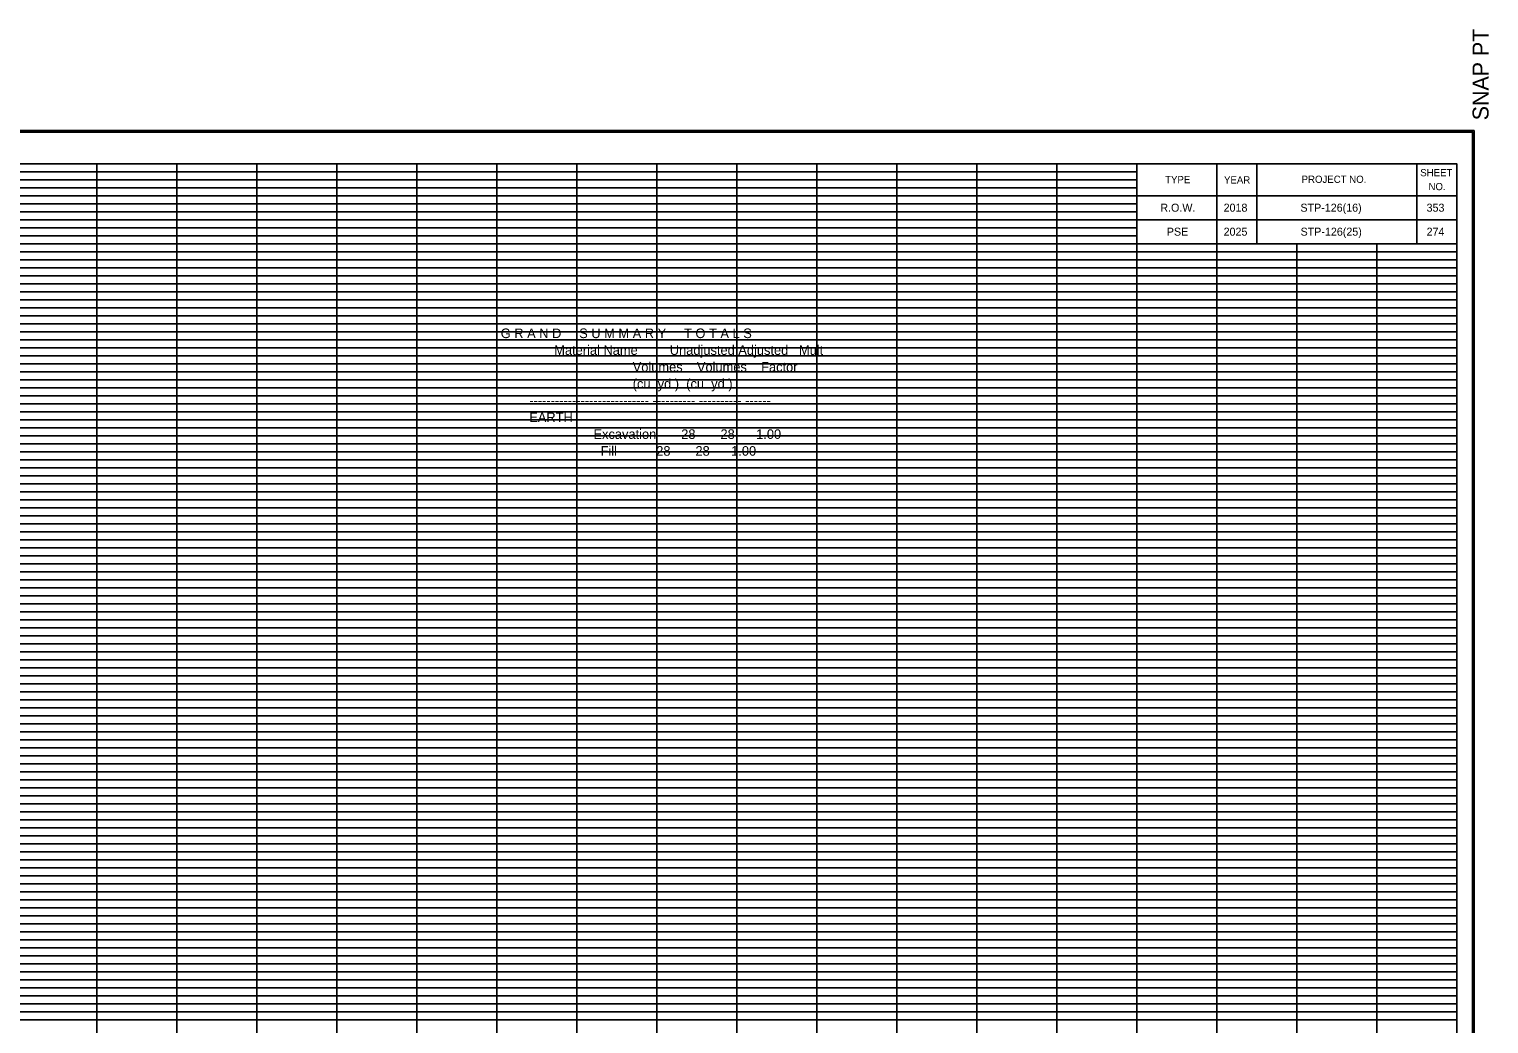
# Model space of a CAD drawing. Extents: x 980 to 1324, y 978 to 1227.
# Drawn here: x 1141.5 to 1324, y 1102.5 to 1226.8 of the extents above; entities that cross this region are included whole.
import ezdxf

# ---------------------------------------------------------------- set-up
doc = ezdxf.new("R2010")
doc.units = 0
for name, color, linetype in [('DESIGN - SCRATCH - User 1', 7, 'Continuous'), ('DESIGN - SHEET - Corner Text', 7, 'Continuous'), ('DESIGN - SHEET - Light Grid', 7, 'Continuous'), ('DESIGN - SHEET - Linework', 7, 'Continuous'), ('DESIGN - SHEET - Plot Shape', 7, 'Continuous'), ('DESIGN - TYPICAL - Finished Grade and Subgrade', 7, 'Continuous'), ('DESIGN - TYPICAL - Text', 7, 'Continuous')]:
    doc.layers.add(name, color=color, linetype=linetype)

# ---------------------------------------------------------------- blocks, each defined once
blk = doc.blocks.new('XSTSHT')
at = {"layer": 'DESIGN - SCRATCH - User 1'}
for p, q in [((28.5, 20.45), (28.5, 20.45)), ((29.24, 20.45), (29.24, 20.45)), ((30.49, 20.45), (30.49, 20.45)), ((31.74, 20.45), (31.74, 20.45)), ((28.5, 20.15), (28.5, 20.15)), ((29.24, 20.15), (29.24, 20.15)), ((30.49, 20.15), (30.49, 20.15)), ((31.74, 20.15), (31.74, 20.15))]:
    blk.add_line(p, q, dxfattribs=at)
at = {"layer": 'DESIGN - SHEET - Light Grid'}
for p, q in [((8, 20.9), (16, 20.9)), ((8, 20.8), (16, 20.8)), ((16, 20.9), (24, 20.9)), ((16, 20.8), (24, 20.8)), ((24, 20.9), (28, 20.9)), ((24, 20.8), (28, 20.8)), ((8, 20.7), (16, 20.7)), ((16, 20.7), (24, 20.7)), ((24, 20.7), (28, 20.7)), ((8, 20.6), (16, 20.6)), ((8, 20.5), (16, 20.5)), ((16, 20.6), (24, 20.6)), ((16, 20.5), (24, 20.5)), ((24, 20.6), (28, 20.6)), ((24, 20.5), (28, 20.5)), ((8, 20.4), (16, 20.4)), ((8, 20.3), (16, 20.3)), ((16, 20.4), (24, 20.4)), ((16, 20.3), (24, 20.3)), ((24, 20.4), (28, 20.4)), ((24, 20.3), (28, 20.3)), ((8, 20.2), (16, 20.2)), ((8, 20.1), (16, 20.1)), ((16, 20.2), (24, 20.2)), ((16, 20.1), (24, 20.1)), ((24, 20.2), (28, 20.2)), ((24, 20.1), (28, 20.1)), ((8, 19.9), (16, 19.9)), ((16, 19.9), (24, 19.9)), ((24, 19.9), (32, 19.9)), ((8, 19.8), (16, 19.8)), ((16, 19.8), (24, 19.8)), ((24, 19.8), (32, 19.8)), ((8, 19.7), (16, 19.7)), ((8, 19.6), (16, 19.6)), ((16, 19.7), (24, 19.7)), ((16, 19.6), (24, 19.6)), ((24, 19.7), (32, 19.7)), ((24, 19.6), (32, 19.6)), ((8, 19.5), (16, 19.5)), ((8, 19.4), (16, 19.4)), ((16, 19.5), (24, 19.5)), ((16, 19.4), (24, 19.4)), ((24, 19.5), (32, 19.5)), ((24, 19.4), (32, 19.4)), ((8, 19.3), (16, 19.3)), ((8, 19.2), (16, 19.2)), ((16, 19.3), (24, 19.3)), ((16, 19.2), (24, 19.2)), ((24, 19.3), (32, 19.3)), ((24, 19.2), (32, 19.2)), ((8, 19.1), (16, 19.1)), ((16, 19.1), (24, 19.1)), ((24, 19.1), (32, 19.1)), ((8, 18.9), (16, 18.9)), ((8, 18.8), (16, 18.8)), ((16, 18.9), (24, 18.9)), ((16, 18.8), (24, 18.8)), ((24, 18.9), (32, 18.9)), ((24, 18.8), (32, 18.8)), ((8, 18.7), (16, 18.7)), ((16, 18.7), (24, 18.7)), ((24, 18.7), (32, 18.7)), ((8, 18.6), (16, 18.6)), ((8, 18.5), (16, 18.5)), ((16, 18.6), (24, 18.6)), ((16, 18.5), (24, 18.5)), ((24, 18.6), (32, 18.6)), ((24, 18.5), (32, 18.5)), ((8, 18.4), (16, 18.4)), ((8, 18.3), (16, 18.3)), ((16, 18.4), (24, 18.4)), ((16, 18.3), (24, 18.3)), ((24, 18.4), (32, 18.4)), ((24, 18.3), (32, 18.3)), ((8, 18.2), (16, 18.2)), ((8, 18.1), (16, 18.1)), ((16, 18.2), (24, 18.2)), ((16, 18.1), (24, 18.1)), ((24, 18.2), (32, 18.2)), ((24, 18.1), (32, 18.1)), ((8, 17.9), (16, 17.9)), ((16, 17.9), (24, 17.9)), ((24, 17.9), (32, 17.9)), ((8, 17.8), (16, 17.8)), ((8, 17.7), (16, 17.7)), ((16, 17.8), (24, 17.8)), ((16, 17.7), (24, 17.7)), ((24, 17.8), (32, 17.8)), ((24, 17.7), (32, 17.7)), ((8, 17.6), (16, 17.6)), ((16, 17.6), (24, 17.6)), ((24, 17.6), (32, 17.6)), ((8, 17.5), (16, 17.5)), ((8, 17.4), (16, 17.4)), ((16, 17.5), (24, 17.5)), ((16, 17.4), (24, 17.4)), ((24, 17.5), (32, 17.5)), ((24, 17.4), (32, 17.4)), ((8, 17.3), (16, 17.3)), ((8, 17.2), (16, 17.2)), ((16, 17.3), (24, 17.3)), ((16, 17.2), (24, 17.2)), ((24, 17.3), (32, 17.3)), ((24, 17.2), (32, 17.2)), ((8, 17.1), (16, 17.1)), ((16, 17.1), (24, 17.1)), ((24, 17.1), (32, 17.1)), ((8, 16.9), (16, 16.9)), ((8, 16.8), (16, 16.8)), ((16, 16.9), (24, 16.9)), ((16, 16.8), (24, 16.8)), ((24, 16.9), (32, 16.9)), ((24, 16.8), (32, 16.8)), ((8, 16.7), (16, 16.7)), ((16, 16.7), (24, 16.7)), ((24, 16.7), (32, 16.7)), ((8, 16.6), (16, 16.6)), ((8, 16.5), (16, 16.5)), ((16, 16.6), (24, 16.6)), ((16, 16.5), (24, 16.5)), ((24, 16.6), (32, 16.6)), ((24, 16.5), (32, 16.5)), ((8, 16.4), (16, 16.4)), ((8, 16.3), (16, 16.3)), ((16, 16.4), (24, 16.4)), ((16, 16.3), (24, 16.3)), ((24, 16.4), (32, 16.4)), ((24, 16.3), (32, 16.3)), ((8, 16.2), (16, 16.2)), ((8, 16.1), (16, 16.1)), ((16, 16.2), (24, 16.2)), ((16, 16.1), (24, 16.1)), ((24, 16.2), (32, 16.2)), ((24, 16.1), (32, 16.1)), ((8, 15.9), (16, 15.9)), ((16, 15.9), (24, 15.9)), ((24, 15.9), (32, 15.9)), ((8, 15.8), (16, 15.8)), ((8, 15.7), (16, 15.7)), ((16, 15.8), (24, 15.8)), ((16, 15.7), (24, 15.7)), ((24, 15.8), (32, 15.8)), ((24, 15.7), (32, 15.7)), ((8, 15.6), (16, 15.6)), ((16, 15.6), (24, 15.6)), ((24, 15.6), (32, 15.6)), ((8, 15.5), (16, 15.5)), ((8, 15.4), (16, 15.4)), ((16, 15.5), (24, 15.5)), ((16, 15.4), (24, 15.4)), ((24, 15.5), (32, 15.5)), ((24, 15.4), (32, 15.4)), ((8, 15.3), (16, 15.3)), ((8, 15.2), (16, 15.2)), ((16, 15.3), (24, 15.3)), ((16, 15.2), (24, 15.2)), ((24, 15.3), (32, 15.3)), ((24, 15.2), (32, 15.2)), ((8, 15.1), (16, 15.1)), ((16, 15.1), (24, 15.1)), ((24, 15.1), (32, 15.1)), ((8, 14.9), (16, 14.9)), ((8, 14.8), (16, 14.8)), ((16, 14.9), (24, 14.9)), ((16, 14.8), (24, 14.8)), ((24, 14.9), (32, 14.9)), ((24, 14.8), (32, 14.8)), ((8, 14.7), (16, 14.7)), ((8, 14.6), (16, 14.6)), ((16, 14.7), (24, 14.7)), ((16, 14.6), (24, 14.6)), ((24, 14.7), (32, 14.7)), ((24, 14.6), (32, 14.6)), ((8, 14.5), (16, 14.5)), ((16, 14.5), (24, 14.5)), ((24, 14.5), (32, 14.5)), ((8, 14.4), (16, 14.4)), ((8, 14.3), (16, 14.3)), ((16, 14.4), (24, 14.4)), ((16, 14.3), (24, 14.3)), ((24, 14.4), (32, 14.4)), ((24, 14.3), (32, 14.3)), ((8, 14.2), (16, 14.2)), ((8, 14.1), (16, 14.1)), ((16, 14.2), (24, 14.2)), ((16, 14.1), (24, 14.1)), ((24, 14.2), (32, 14.2)), ((24, 14.1), (32, 14.1)), ((8, 13.9), (16, 13.9)), ((16, 13.9), (24, 13.9)), ((24, 13.9), (32, 13.9)), ((8, 13.8), (16, 13.8)), ((8, 13.7), (16, 13.7)), ((16, 13.8), (24, 13.8)), ((16, 13.7), (24, 13.7)), ((24, 13.8), (32, 13.8)), ((24, 13.7), (32, 13.7)), ((8, 13.6), (16, 13.6)), ((16, 13.6), (24, 13.6)), ((24, 13.6), (32, 13.6)), ((8, 13.5), (16, 13.5)), ((8, 13.4), (16, 13.4)), ((16, 13.5), (24, 13.5)), ((16, 13.4), (24, 13.4)), ((24, 13.5), (32, 13.5)), ((24, 13.4), (32, 13.4)), ((8, 13.3), (16, 13.3)), ((8, 13.2), (16, 13.2)), ((16, 13.3), (24, 13.3)), ((16, 13.2), (24, 13.2)), ((24, 13.3), (32, 13.3)), ((24, 13.2), (32, 13.2)), ((8, 13.1), (16, 13.1)), ((16, 13.1), (24, 13.1)), ((24, 13.1), (32, 13.1)), ((8, 12.9), (16, 12.9)), ((8, 12.8), (16, 12.8)), ((16, 12.9), (24, 12.9)), ((16, 12.8), (24, 12.8)), ((24, 12.9), (32, 12.9)), ((24, 12.8), (32, 12.8)), ((8, 12.7), (16, 12.7)), ((8, 12.6), (16, 12.6)), ((16, 12.7), (24, 12.7)), ((16, 12.6), (24, 12.6)), ((24, 12.7), (32, 12.7)), ((24, 12.6), (32, 12.6)), ((8, 12.5), (16, 12.5)), ((16, 12.5), (24, 12.5)), ((24, 12.5), (32, 12.5)), ((8, 12.4), (16, 12.4)), ((8, 12.3), (16, 12.3)), ((16, 12.4), (24, 12.4)), ((16, 12.3), (24, 12.3)), ((24, 12.4), (32, 12.4)), ((24, 12.3), (32, 12.3)), ((8, 12.2), (16, 12.2)), ((8, 12.1), (16, 12.1)), ((16, 12.2), (24, 12.2)), ((16, 12.1), (24, 12.1)), ((24, 12.2), (32, 12.2)), ((24, 12.1), (32, 12.1)), ((8, 11.9), (16, 11.9)), ((16, 11.9), (24, 11.9)), ((24, 11.9), (32, 11.9)), ((8, 11.8), (16, 11.8)), ((8, 11.7), (16, 11.7)), ((16, 11.8), (24, 11.8)), ((16, 11.7), (24, 11.7)), ((24, 11.8), (32, 11.8)), ((24, 11.7), (32, 11.7)), ((8, 11.6), (16, 11.6)), ((8, 11.5), (16, 11.5)), ((16, 11.6), (24, 11.6)), ((16, 11.5), (24, 11.5)), ((24, 11.6), (32, 11.6)), ((24, 11.5), (32, 11.5)), ((8, 11.4), (16, 11.4)), ((16, 11.4), (24, 11.4)), ((24, 11.4), (32, 11.4)), ((8, 11.3), (16, 11.3)), ((8, 11.2), (16, 11.2)), ((16, 11.3), (24, 11.3)), ((16, 11.2), (24, 11.2)), ((24, 11.3), (32, 11.3)), ((24, 11.2), (32, 11.2)), ((8, 11.1), (16, 11.1)), ((16, 11.1), (24, 11.1)), ((24, 11.1), (32, 11.1)), ((8, 10.9), (16, 10.9)), ((8, 10.8), (16, 10.8)), ((16, 10.9), (24, 10.9)), ((16, 10.8), (24, 10.8)), ((24, 10.9), (32, 10.9)), ((24, 10.8), (32, 10.8)), ((8, 10.7), (16, 10.7)), ((8, 10.6), (16, 10.6)), ((16, 10.7), (24, 10.7)), ((16, 10.6), (24, 10.6)), ((24, 10.7), (32, 10.7)), ((24, 10.6), (32, 10.6)), ((8, 10.5), (16, 10.5)), ((8, 10.4), (16, 10.4)), ((16, 10.5), (24, 10.5)), ((16, 10.4), (24, 10.4)), ((24, 10.5), (32, 10.5)), ((24, 10.4), (32, 10.4)), ((8, 10.3), (16, 10.3)), ((16, 10.3), (24, 10.3)), ((24, 10.3), (32, 10.3))]:
    blk.add_line(p, q, dxfattribs=at)
at = {"layer": 'DESIGN - SHEET - Linework'}
for p, q in [((-1.823, 21.414), (32.217, 21.414)), ((32.217, 21.414), (32.217, -0.414)), ((15, 0), (15, 21)), ((16, 0), (16, 21)), ((17, 0), (17, 21)), ((18, 0), (18, 21)), ((19, 0), (19, 21)), ((20, 0), (20, 21)), ((21, 0), (21, 21)), ((22, 0), (22, 21)), ((23, 0), (23, 21)), ((24, 0), (24, 21)), ((25, 0), (25, 21)), ((26, 0), (26, 21)), ((27, 0), (27, 21)), ((0, 20), (28, 20)), ((28, 0), (28, 20)), ((29, 0), (29, 20)), ((30, 0), (30, 20)), ((31, 0), (31, 20)), ((0, 19), (32, 19)), ((0, 18), (32, 18)), ((0, 17), (32, 17)), ((0, 16), (32, 16)), ((0, 15), (32, 15)), ((0, 14), (32, 14)), ((0, 13), (32, 13)), ((0, 12), (32, 12)), ((0, 11), (32, 11))]:
    blk.add_line(p, q, dxfattribs=at)
for points in [[(0, 21), (0, 0), (32, 0), (32, 21), (0, 21)], [(28, 21), (28, 20), (32, 20), (32, 21), (31.5, 21), (31.5, 20), (29.5, 20), (29.5, 21), (29, 21), (29, 20), (32, 20), (28, 20), (28, 20.3), (32, 20.3), (32, 20.6), (28, 20.6)]]:
    blk.add_lwpolyline(points, dxfattribs=at)
at = {"layer": 'DESIGN - SHEET - Plot Shape'}
for points in [[(-1.803, 21.394), (32.197, 21.394), (32.197, -0.394), (-1.803, -0.394)], [(-0.85, 21), (32, 21), (32, -0.25), (-0.85, -0.25)]]:
    blk.add_lwpolyline(points, close=True, dxfattribs=at)
at = {"layer": 'DESIGN - SHEET - Corner Text'}
blk.add_text('  SNAP PT', height=0.2, rotation=90, dxfattribs=at).set_placement((32.397, 21.394))
for s, p in [('TYPE', (28.354, 20.756)), ('YEAR', (29.09, 20.752)), ('PROJECT NO.', (30.06, 20.76)), ('SHEET', (31.543, 20.843)), ('NO.', (31.646, 20.669))]:
    blk.add_text(s, height=0.09, dxfattribs=at).set_placement(p)

msp = doc.modelspace()

# ---------------------------------------------------------------- block references
at = {"layer": 'DESIGN - TYPICAL - Finished Grade and Subgrade', "xscale": 10, "yscale": 10}
msp.add_blockref('XSTSHT', (1000, 1000), dxfattribs=at)

# ---------------------------------------------------------------- texts
at = {"layer": 'DESIGN - SHEET - Corner Text'}
for s, p in [('R.O.W.', (1282.94, 1204)), ('2018', (1290.85, 1204)), ('STP-126(16)', (1300.45, 1204)), ('353', (1316.22, 1204)), ('PSE', (1283.75, 1201)), ('2025', (1290.85, 1201)), ('STP-126(25)', (1300.47, 1201)), ('274', (1316.22, 1201))]:
    msp.add_text(s, height=1, dxfattribs=at).set_placement(p)
at = {"layer": 'DESIGN - TYPICAL - Text'}
for s, p in [('G R A N D     S U M M A R Y     T O T A L S', (1200.49, 1188.2)), ('               Material Name         Unadjusted Adjusted   Mult', (1200.49, 1186.1)), ('                                     Volumes    Volumes    Factor', (1200.49, 1184)), ('                                     (cu. yd.)  (cu. yd.)', (1200.49, 1181.9)), ('        ---------------------------- ---------- ---------- ------', (1200.49, 1179.8)), ('        EARTH', (1200.49, 1177.7)), ('                          Excavation       28       28      1.00', (1200.49, 1175.6)), ('                            Fill           28       28      1.00', (1200.49, 1173.5))]:
    msp.add_text(s, height=1.2, dxfattribs=at).set_placement(p)

doc.saveas('drawing.dxf')
